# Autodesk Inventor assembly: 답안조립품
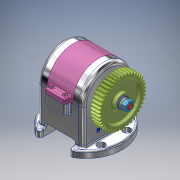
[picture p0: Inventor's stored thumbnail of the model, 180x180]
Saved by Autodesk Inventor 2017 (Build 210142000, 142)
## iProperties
Part Number: 답안조립품
Material: 일반
Document SubType Name: Assembly
Designer: MRC
Author: MRC
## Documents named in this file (21)
- C:\Users\MRC\Desktop\740804V1001\답안조립품.iam
- C:\Users\MRC\Desktop\740804V1001\본체.ipt
- C:\Users\MRC\Desktop\740804V1001\오일레스 부시 20 15.ipt
- C:\Users\MRC\Desktop\740804V1001\부시 커버.ipt
- C:\Users\MRC\Desktop\740804V1001\육각 소켓 머리 볼트 M4x10.ipt
- C:\Users\MRC\Desktop\740804V1001\링크.ipt
- C:\Users\MRC\Desktop\740804V1001\펀치.ipt
- C:\Users\MRC\Desktop\740804V1001\핀.ipt
- C:\Users\MRC\Desktop\740804V1001\E형 멈춤링 10-8.ipt
- C:\Users\MRC\Desktop\740804V1001\깊은 홈 볼 베어링 6904.ipt
- C:\Users\MRC\Desktop\740804V1001\칼라.ipt
- C:\Users\MRC\Desktop\740804V1001\편심축.ipt
- C:\Users\MRC\Desktop\740804V1001\뒷커버.ipt
- C:\Users\MRC\Desktop\740804V1001\오일실 20 32 5.ipt
- C:\Users\MRC\Desktop\740804V1001\앞커버.ipt
- C:\Users\MRC\Desktop\740804V1001\평행키 5x5x12.ipt
- C:\Users\MRC\Desktop\740804V1001\스퍼 기어.ipt
- C:\Users\MRC\Desktop\740804V1001\평와셔 M10.ipt
- C:\Users\MRC\Desktop\740804V1001\스프링 와셔 M10.ipt
- C:\Users\MRC\Desktop\740804V1001\육각 너트 M10x1.ipt
- C:\Users\MRC\Desktop\740804V1001\윗커버.ipt
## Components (2 placed, 2 different names)
1. 핀:1
2. E형 멈춤링 10-8:1
